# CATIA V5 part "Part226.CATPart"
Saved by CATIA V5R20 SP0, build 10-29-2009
Part number: FA 168700-2 comprimido
Revision: ANY
Definition: UNKNOWN
Nomenclature: FA 168700-2 comprimido
Source: Unknown
Bounding box of the stored display mesh (mm): x -2.8 to 2.8, y 0 to 4.04, z -2.8 to 2.8
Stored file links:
  C:\Users\Utente\Desktop\IO LAVORO\3D X SITO CF\CUMSA\3D files FA\FA 200712-20\Part226.CATPart
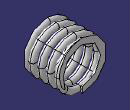
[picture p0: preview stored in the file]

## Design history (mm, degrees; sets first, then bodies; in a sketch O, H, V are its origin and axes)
Body1 "Cortar-Extruir1" (main body)
  Solid1: solid without history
